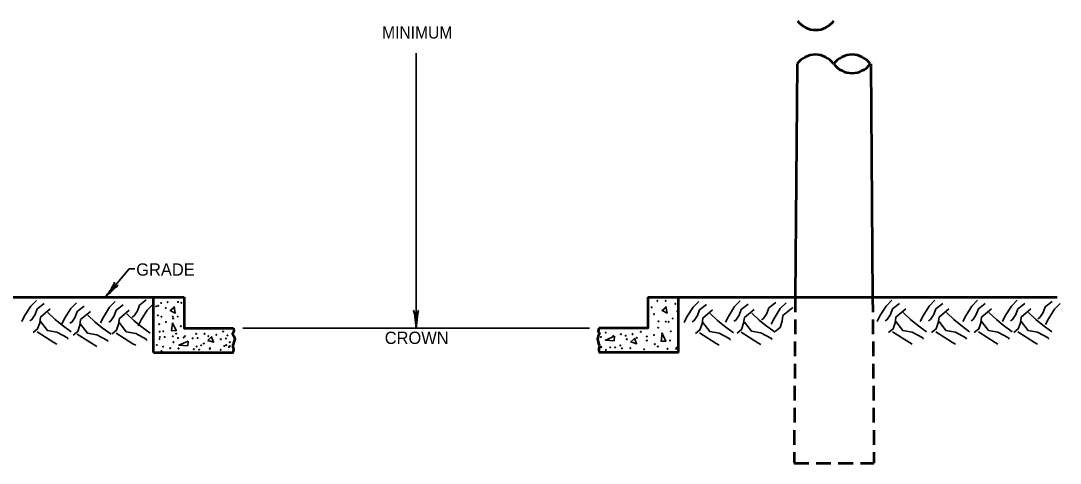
# Model space of a CAD drawing. Extents: x -421 to 434, y -46 to 498.
# Drawn here: x -181.8 to 21.2, y 231.2 to 317.6 of the extents above; entities that cross this region are included whole.
import ezdxf
from ezdxf.enums import TextEntityAlignment as Align

# ---------------------------------------------------------------- set-up
doc = ezdxf.new("R2010")
doc.units = 0
doc.header["$LTSCALE"] = 0.96
doc.linetypes.add('MEDIUM_DASHED', pattern=[4.5, 3, -1.5])
doc.layers.add('1', color=7, linetype='Continuous', lineweight=53)

msp = doc.modelspace()

# ---------------------------------------------------------------- linework, layer by layer
at = {"layer": '1', "lineweight": 35}
for p, q in [((-104.5875, 257.5862), (-104.5875, 311.2579)), ((-138.42, 257.5862), (-70.7262, 257.5862))]:
    msp.add_line(p, q, dxfattribs=at)
at = {"layer": '1'}
for p, q in [((-30.1996, 309.1862), (-30.5504, 263.5862)), ((-15.7996, 309.1862), (-15.4488, 263.5862)), ((-226.1504, 263.5862), (-149.8488, 263.5862)), ((-155.8488, 252.7862), (-155.8488, 263.5862)), ((-59.3504, 263.5862), (20.5512, 263.5862)), ((-53.3262, 252.7862), (-53.3262, 263.5862)), ((-155.8488, 252.7862), (-140.2488, 252.7862)), ((-53.3262, 252.7862), (-68.9262, 252.7862))]:
    msp.add_line(p, q, dxfattribs=at)
at = {"layer": '1', "linetype": 'MEDIUM_DASHED'}
for p, q in [((-30.5504, 263.5862), (-30.7996, 231.1862)), ((-15.4488, 263.5862), (-15.1996, 231.1862)), ((-30.7996, 231.1862), (-15.1996, 231.1862))]:
    msp.add_line(p, q, dxfattribs=at)
at = {"layer": '1', "lineweight": 35}
for points in [[(-165.298, 263.5542), (-160.634, 269.1291), (-159.5273, 269.1291)], [(-178.7166, 262.9886), (-179.8334, 261.8715), (-181.03, 259.9563), (-181.5884, 258.8392)], [(-177.2009, 262.3503), (-178.5571, 261.3129), (-178.9559, 260.1957), (-179.5941, 259.2382), (-179.9929, 258.9988)], [(-170.8991, 262.5098), (-172.0159, 261.3927), (-173.2125, 259.4775), (-173.7709, 258.3604)], [(-169.3834, 261.8715), (-170.7396, 260.8341), (-171.1384, 259.7169), (-171.7766, 258.7594), (-172.1754, 258.52)], [(-163.3207, 262.7492), (-164.4375, 261.6321), (-165.6341, 259.7169), (-166.1925, 258.5998)], [(-161.805, 262.1109), (-163.1612, 261.0735), (-163.56, 259.9563), (-164.1982, 258.9988), (-164.597, 258.7594)], [(-157.2578, 263.0685), (-158.614, 262.0311), (-159.0128, 260.9139), (-159.651, 259.9564), (-160.0498, 259.717)], [(-155.9816, 262.1906), (-157.0984, 261.0735), (-158.295, 259.1583), (-158.8534, 258.0412)], [(-151.6986, 261.7013), (-152.5775, 261.0343), (-151.6077, 260.5189), (-151.8198, 261.8225)], [(-55.6924, 261.7013), (-56.5713, 261.0343), (-55.6015, 260.5189), (-55.8136, 261.8225)], [(-49.4047, 262.7953), (-50.5215, 261.6782), (-51.7181, 259.763), (-52.2765, 258.6459)], [(-47.889, 262.157), (-49.2452, 261.1196), (-49.644, 260.0024), (-50.2822, 259.0449), (-50.681, 258.8055)], [(-41.2848, 262.8956), (-42.4016, 261.7785), (-43.5982, 259.8633), (-44.1566, 258.7462)], [(-39.7691, 262.2573), (-41.1253, 261.2199), (-41.5241, 260.1027), (-42.1623, 259.1452), (-42.5611, 258.9058)], [(-34.3558, 262.5582), (-35.712, 261.5208), (-36.1108, 260.4036), (-36.749, 259.4461), (-37.1478, 259.2067)], [(-32.363, 262.4945), (-33.4798, 261.3774), (-34.6764, 259.4622), (-35.2348, 258.3451)], [(-11.7125, 262.9959), (-12.8293, 261.8788), (-14.0259, 259.9636), (-14.5843, 258.8465)], [(-10.1968, 262.3576), (-11.553, 261.3202), (-11.9518, 260.203), (-12.59, 259.2455), (-12.9888, 259.0061)], [(-3.2918, 262.9959), (-4.4086, 261.8788), (-5.6052, 259.9636), (-6.1636, 258.8465)], [(-1.7761, 262.3576), (-3.1323, 261.3202), (-3.5311, 260.203), (-4.1693, 259.2455), (-4.5681, 259.0061)], [(5.0286, 262.996), (3.9118, 261.8789), (2.7152, 259.9637), (2.1568, 258.8466)], [(6.5443, 262.3577), (5.1881, 261.3203), (4.7893, 260.2031), (4.1511, 259.2456), (3.7523, 259.0062)], [(12.7476, 262.996), (11.6308, 261.8789), (10.4342, 259.9637), (9.8758, 258.8466)], [(14.2633, 262.3577), (12.9071, 261.3203), (12.5083, 260.2031), (11.8701, 259.2456), (11.4713, 259.0062)], [(19.5763, 262.7589), (18.2201, 261.7215), (17.8213, 260.6043), (17.1831, 259.6468), (16.7843, 259.4074)], [(21.1682, 262.3943), (20.0514, 261.2772), (18.8548, 259.362), (18.2964, 258.2449)], [(-176.0044, 261.3129), (-177.9189, 259.7169), (-178.0784, 258.5998), (-178.4773, 257.4028), (-179.3548, 256.6846)], [(-176.483, 260.5947), (-175.0471, 259.2382), (-173.691, 258.121), (-171.936, 256.8442)], [(-168.1869, 260.8341), (-170.1014, 259.2381), (-170.2609, 258.121), (-170.6598, 256.924), (-171.5373, 256.2058)], [(-168.6655, 260.1159), (-167.2296, 258.7594), (-165.8735, 257.6422), (-164.1185, 256.3654)], [(-160.6085, 261.0735), (-162.523, 259.4775), (-162.6825, 258.3604), (-163.0814, 257.1634), (-163.9589, 256.4452)], [(-161.0871, 260.3553), (-159.6512, 258.9988), (-158.2951, 257.8816), (-156.5401, 256.6048)], [(-46.6925, 261.1196), (-48.607, 259.5236), (-48.7665, 258.4065), (-49.1654, 257.2095), (-50.0429, 256.4913)], [(-47.1711, 260.4014), (-45.7352, 259.0449), (-44.3791, 257.9277), (-42.6241, 256.6509)], [(-38.5726, 261.2199), (-40.4871, 259.6239), (-40.6466, 258.5068), (-41.0455, 257.3098), (-41.923, 256.5916)], [(-39.0512, 260.5017), (-37.6153, 259.1452), (-36.2592, 258.028), (-34.5042, 256.7512)], [(-31.0542, 261.621), (-32.9687, 260.025), (-33.1282, 258.9079), (-33.5271, 257.7109), (-34.4046, 256.9927)], [(-9.0003, 261.3202), (-10.9148, 259.7242), (-11.0743, 258.6071), (-11.4732, 257.4101), (-12.3507, 256.6919)], [(-9.4789, 260.602), (-8.043, 259.2455), (-6.6869, 258.1283), (-4.9319, 256.8515)], [(-0.5796, 261.3202), (-2.4941, 259.7242), (-2.6536, 258.6071), (-3.0525, 257.4101), (-3.93, 256.6919)], [(-1.0582, 260.602), (0.3777, 259.2455), (1.7338, 258.1283), (3.4888, 256.8515)], [(7.7408, 261.3203), (5.8263, 259.7243), (5.6668, 258.6072), (5.2679, 257.4102), (4.3904, 256.692)], [(7.2622, 260.6021), (8.6981, 259.2456), (10.0542, 258.1284), (11.8092, 256.8516)], [(15.4598, 261.3203), (13.5453, 259.7243), (13.3858, 258.6072), (12.9869, 257.4102), (12.1094, 256.692)], [(14.9812, 260.6021), (16.4171, 259.2456), (17.7732, 258.1284), (19.5282, 256.8516)], [(-177.9189, 258.8392), (-176.5628, 257.0836), (-174.728, 256.7644), (-172.6539, 255.6473), (-172.5742, 255.4079)], [(-170.1014, 258.3604), (-168.7453, 256.6048), (-166.9105, 256.2856), (-164.8364, 255.1685), (-164.7567, 254.9291)], [(-162.523, 258.5998), (-161.1669, 256.8442), (-159.3321, 256.525), (-157.258, 255.4079), (-157.1783, 255.1685)], [(-48.607, 258.6459), (-47.2509, 256.8903), (-45.4161, 256.5711), (-43.342, 255.454), (-43.2623, 255.2146)], [(-40.4871, 258.7462), (-39.131, 256.9906), (-37.2962, 256.6714), (-35.2221, 255.5543), (-35.1424, 255.3149)], [(-10.9148, 258.8465), (-9.5587, 257.0909), (-7.7239, 256.7717), (-5.6498, 255.6546), (-5.5701, 255.4152)], [(-2.4941, 258.8465), (-1.138, 257.0909), (0.6968, 256.7717), (2.7709, 255.6546), (2.8506, 255.4152)], [(5.8263, 258.8466), (7.1824, 257.091), (9.0172, 256.7718), (11.0913, 255.6547), (11.171, 255.4153)], [(13.5453, 258.8466), (14.9014, 257.091), (16.7362, 256.7718), (18.8103, 255.6547), (18.89, 255.4153)], [(-178.5571, 256.8442), (-175.2864, 254.7695), (-174.728, 254.4503)], [(-170.7396, 256.3654), (-167.4689, 254.2907), (-166.9105, 253.9715)], [(-163.1612, 256.6048), (-159.8905, 254.5301), (-159.3321, 254.2109)], [(-144.455, 255.9106), (-145.243, 255.1527), (-144.1217, 254.8192), (-144.5157, 255.8803)], [(-65.8344, 256.0124), (-67.6226, 255.2241), (-65.9253, 255.1029), (-65.8344, 255.9821)], [(-49.2452, 256.6509), (-45.9745, 254.5762), (-45.4161, 254.257)], [(-41.1253, 256.7512), (-37.8546, 254.6765), (-37.2962, 254.3573)], [(-11.553, 256.8515), (-8.2823, 254.7768), (-7.7239, 254.4576)], [(-3.1323, 256.8515), (0.1384, 254.7768), (0.6968, 254.4576)], [(5.1881, 256.8516), (8.4588, 254.7769), (9.0172, 254.4577)], [(12.9071, 256.8516), (16.1778, 254.7769), (16.7362, 254.4577)], [(-149.0921, 255.0314), (-150.8803, 254.2431), (-149.183, 254.1219), (-149.0921, 255.0011)], [(-61.8838, 255.6163), (-62.6718, 254.8584), (-61.5505, 254.5249), (-61.9445, 255.586)]]:
    msp.add_lwpolyline(points, dxfattribs=at)
at = {"layer": '1'}
for points in [[(-149.8488, 263.5862), (-149.8488, 257.5862), (-140.2488, 257.5862)], [(-59.3262, 263.5862), (-59.3262, 257.5862), (-68.9262, 257.5862)], [(-140.2488, 257.5862), (-140.1658, 256.9436), (-140.4104, 256.4217), (-140.1495, 255.9649), (-140.0027, 255.4103), (-140.1658, 254.8884), (-140.2147, 254.5621), (-140.3451, 254.2196), (-140.3778, 253.8607), (-140.2636, 253.616), (-140.2473, 253.3061), (-140.3451, 252.8657), (-140.2488, 252.7862)], [(-68.9262, 257.5862), (-69.0092, 256.9436), (-68.7646, 256.4217), (-69.0255, 255.9649), (-69.1723, 255.4103), (-69.0092, 254.8884), (-68.9603, 254.5621), (-68.8299, 254.2196), (-68.7972, 253.8607), (-68.9114, 253.616), (-68.9277, 253.3061), (-68.8299, 252.8657), (-68.9262, 252.7862)]]:
    msp.add_lwpolyline(points, dxfattribs=at)
at = {"layer": '1', "lineweight": 35}
for points in [[(-152.1532, 258.6089), (-152.3654, 257.0627), (-151.4258, 257.093)], [(-56.5393, 256.5489), (-56.7515, 255.0027), (-55.8119, 255.033)]]:
    msp.add_lwpolyline(points, close=True, dxfattribs=at)
for centre in [(-155.3355, 261.8225), (-154.9415, 261.9134), (-154.3657, 262.4591), (-153.0927, 262.641), (-151.0621, 262.6714), (-150.4257, 262.5198), (-57.4855, 262.9122), (-55.8672, 262.8833), (-53.9889, 262.3051), (-155.0021, 260.064), (-154.305, 259.7912), (-153.4564, 261.489), (-152.0926, 259.7912), (-151.1227, 259.8215), (-58.5836, 261.6403), (-58.1501, 260.2817), (-53.5843, 260.8598), (-154.7597, 258.3359), (-153.4261, 258.7604), (-152.032, 259.4577), (-150.5166, 257.9418), (-57.2543, 258.8941), (-55.8383, 258.8363), (-55.2892, 258.8074), (-54.4801, 259.4434), (-154.6384, 256.8807), (-154.6081, 255.8499), (-153.9414, 256.9413), (-153.6686, 255.8196), (-152.0926, 255.9712), (-151.4258, 256.4866), (-151.0621, 255.6377), (-149.971, 255.7286), (-149.6983, 256.0015), (-147.5161, 256.4562), (-147.2433, 255.6377), (-145.9098, 256.4562), (-145.1521, 256.0015), (-143.6064, 256.244), (-142.2426, 256.911), (-141.394, 256.1531), (-68.4954, 255.83), (-67.5707, 256.6972), (-66.068, 256.0323), (-64.6231, 256.3792), (-63.6695, 256.0902), (-62.3402, 256.3792), (-61.5022, 255.6855), (-60.722, 256.8417), (-59.5372, 255.9456), (-58.1501, 256.2347), (-57.3121, 257.6511), (-56.5318, 256.5238), (-54.8558, 256.9574), (-155.193, 254.26), (-154.6687, 255.4558), (-153.9717, 253.9399), (-152.6078, 253.667), (-151.941, 254.8191), (-148.2132, 255.577), (-147.4252, 253.9702), (-146.5463, 254.2127), (-146.031, 254.5765), (-144.8187, 253.667), (-142.6972, 255.4254), (-142.0304, 254.0915), (-141.697, 255.5467), (-141.6667, 254.2734), (-141.6364, 254.243), (-141.1212, 253.8792), (-140.9393, 254.8191), (-140.9393, 254.0308), (-68.4376, 253.8932), (-66.7037, 253.8065), (-65.7212, 253.8065), (-64.7098, 254.1823), (-64.3919, 253.6331), (-63.4383, 255.4253), (-62.7737, 253.662), (-59.5372, 255.1651), (-57.9767, 254.4425), (-57.3988, 253.98), (-55.0292, 255.1362), (-53.6999, 253.7487), (-154.2833, 253.0563), (-150.9712, 253.5761), (-147.9707, 253.4548), (-146.9403, 253.3638), (-144.849, 253.5154), (-142.7578, 253.3335), (-67.5129, 253.2862), (-60.0573, 253.4307), (-55.4915, 253.5175), (-53.8155, 253.5175)]:
    msp.add_circle(centre, 0.0678, dxfattribs=at)
at = {"layer": '1'}
for centre, start, end in [((-26.5673, 320.2424), 216.66818, 323.33182), ((-26.6319, 306.53), 36.66818, 143.33182), ((-19.4727, 306.53), 36.66818, 143.33182), ((-19.4727, 311.8226), 216.66818, 323.33182)]:
    msp.add_arc(centre, 4.4479, start, end, dxfattribs=at)
at = {"layer": '1', "lineweight": 40}
for centre, major_axis, ratio, start_param, end_param in [((-164.7121, 264.7713), (-1.2313, -1.7638), 0.122415, 0.89635335, 3.14159265), ((-164.2405, 264.4226), (-1.5141, -1.4814), 0.07063, 3.14071475, 5.41810995), ((-104.9191, 258.8956), (0.1874, -2.1428), 0.122415, 0.89635335, 3.14159265), ((-104.3336, 258.9308), (-0.2108, -2.1077), 0.07063, 3.14071475, 5.41810995)]:
    msp.add_ellipse(centre, major_axis=major_axis, ratio=ratio, start_param=start_param, end_param=end_param, dxfattribs=at)

# ---------------------------------------------------------------- texts
at = {"layer": '1', "width": 0.95}
msp.add_text('MINIMUM', height=2.4, dxfattribs=at).set_placement((-104.3685, 314.1169), align=Align.CENTER)
at = {"layer": '1'}
for s, p in [('GRADE', (-153.5194, 267.8104)), ('CROWN', (-104.4747, 254.4734))]:
    msp.add_text(s, height=2.4, dxfattribs=at).set_placement(p, align=Align.CENTER)

doc.saveas('drawing.dxf')
